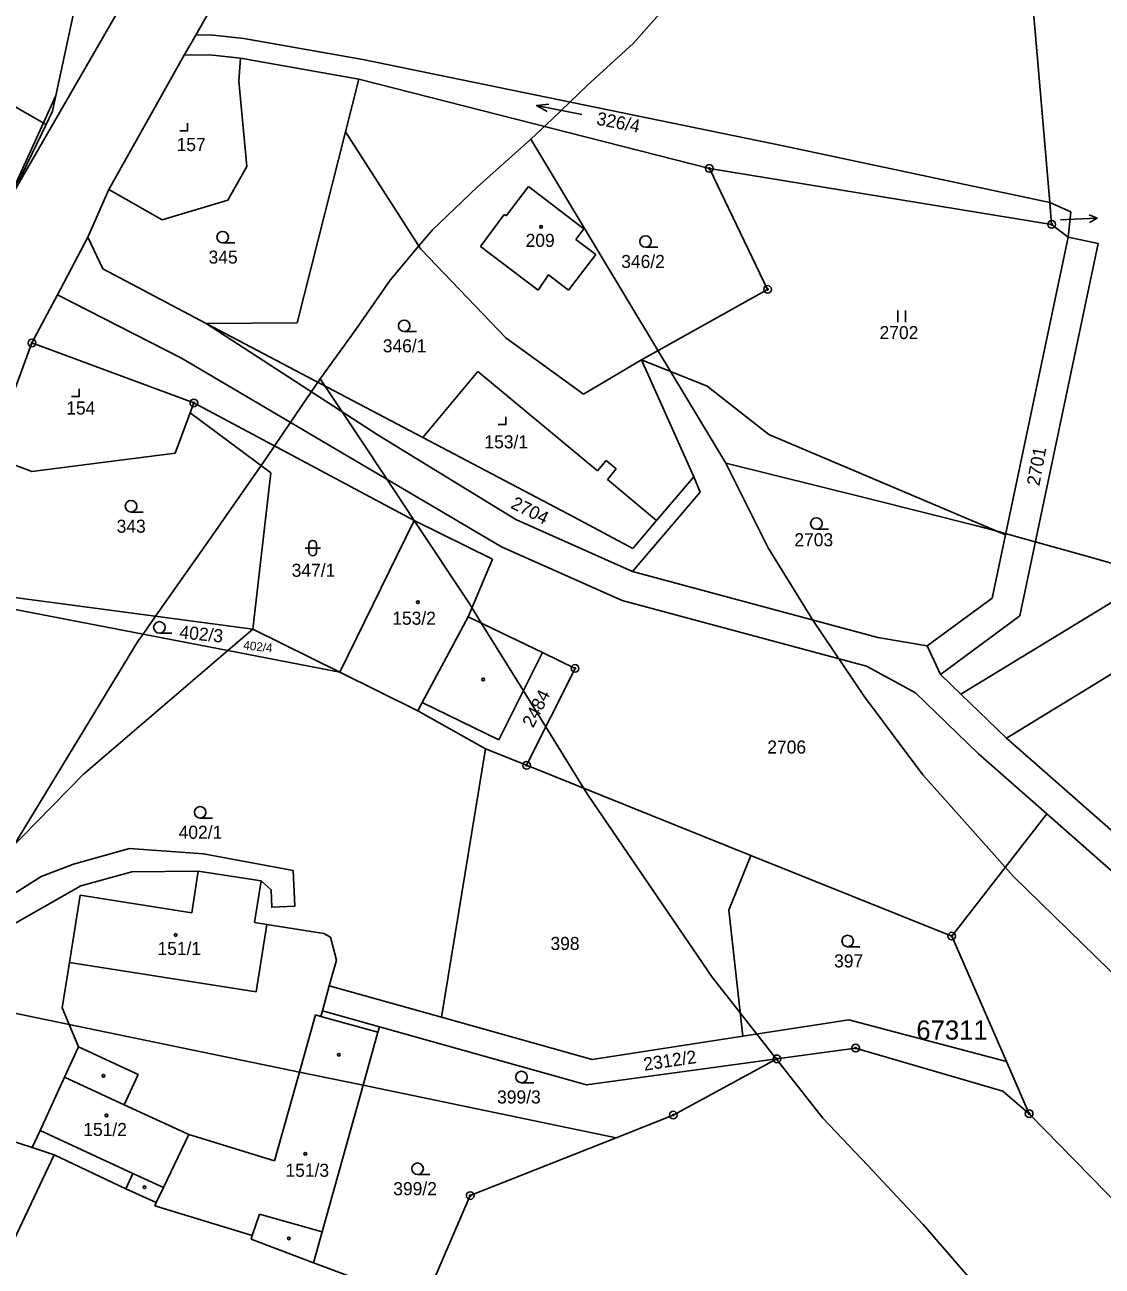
# Model space of a CAD drawing. Extents: x -546762 to -540209, y -1046851 to -1035694.
# Drawn here: x -542448.6 to -542308.1, y -1039131 to -1038969.2 of the extents above; entities that cross this region are included whole.
import ezdxf

# ---------------------------------------------------------------- set-up
doc = ezdxf.new("R2010")
doc.units = 0
for name, color, linetype in [('Vrstva 1', 7, 'Continuous'), ('Vrstva 16', 7, 'Continuous'), ('Vrstva 18', 7, 'Continuous'), ('Vrstva 19', 7, 'Continuous'), ('Vrstva 24', 7, 'Continuous'), ('Vrstva 25', 7, 'Continuous'), ('Vrstva 3', 7, 'Continuous'), ('Vrstva 30', 7, 'Continuous'), ('Vrstva 37', 7, 'Continuous'), ('Vrstva 4', 7, 'Continuous'), ('Vrstva 52', 7, 'Continuous'), ('Vrstva 53', 7, 'Continuous')]:
    doc.layers.add(name, color=color, linetype=linetype)

msp = doc.modelspace()

# ---------------------------------------------------------------- linework, layer by layer
at = {"layer": 'Vrstva 1'}
for p, q in [((-542405.08, -1038976.23), (-542359.35, -1038987.89)), ((-542349.73, -1038984.94), (-542314.95, -1038992.34)), ((-542437.67, -1038990.65), (-542440.39, -1038996.86)), ((-542424.99, -1039008.1), (-542413.11, -1039008.04)), ((-542375.74, -1039017.32), (-542368.19, -1039012.85)), ((-542396.72, -1039022.97), (-542389.53, -1039014.35)), ((-542372.63, -1039028.44), (-542366.22, -1039033.79)), ((-542386.81, -1039062.4), (-542381.12, -1039051.03)), ((-542410.99, -1039130.59), (-542396.61, -1039135.93))]:
    msp.add_line(p, q, dxfattribs=at)
for points in [[(-542450.21, -1038991.24), (-542389.73, -1038886.34)], [(-542426.34, -1038970.5), (-542407.76, -1038937.63)], [(-542440.93, -1038961.4), (-542445, -1038980.42)], [(-542317.12, -1038966.99), (-542314.95, -1038992.34)], [(-542426.34, -1038970.5), (-542427.82, -1038973.12)], [(-542426.34, -1038970.5), (-542424.46, -1038970.47)], [(-542424.46, -1038970.47), (-542420.06, -1038970.96)], [(-542420.06, -1038970.96), (-542404.56, -1038973.68)], [(-542437.67, -1038990.65), (-542427.82, -1038973.12)], [(-542427.82, -1038973.12), (-542424.55, -1038973.07)], [(-542424.55, -1038973.07), (-542420.48, -1038973.53)], [(-542420.48, -1038973.53), (-542420.7, -1038976.52)], [(-542420.48, -1038973.53), (-542405.08, -1038976.23)], [(-542404.56, -1038973.68), (-542349.73, -1038984.94)], [(-542420.7, -1038976.52), (-542419.68, -1038987.63)], [(-542405.08, -1038976.23), (-542406.82, -1038983.11)], [(-542454.29, -1038977.39), (-542445.83, -1038982.14)], [(-542445, -1038980.42), (-542445.83, -1038982.14)], [(-542450.21, -1038991.24), (-542445.83, -1038982.14)], [(-542413.11, -1039008.04), (-542406.82, -1038983.11)], [(-542406.82, -1038983.11), (-542396.96, -1038998.41)], [(-542419.68, -1038987.63), (-542422.16, -1038992.03)], [(-542314.71, -1038995.19), (-542359.35, -1038987.89)], [(-542359.35, -1038987.89), (-542351.76, -1039003.66)], [(-542430.7, -1038994.57), (-542437.67, -1038990.65)], [(-542385.85, -1038994.09), (-542382.94, -1038990.24)], [(-542382.94, -1038990.24), (-542375.7, -1038995.75)], [(-542422.16, -1038992.03), (-542430.7, -1038994.57)], [(-542314.95, -1038992.34), (-542312.2, -1038993.53)], [(-542314.95, -1038992.34), (-542314.71, -1038995.19)], [(-542389.19, -1038998.05), (-542386.09, -1038993.91)], [(-542386.09, -1038993.91), (-542385.85, -1038994.09)], [(-542312.2, -1038993.53), (-542312.56, -1038996.85)], [(-542375.7, -1038995.75), (-542376.75, -1038997.14)], [(-542314.71, -1038995.19), (-542312.56, -1038996.85)], [(-542444.38, -1039004.39), (-542440.39, -1038996.86)], [(-542440.39, -1038996.86), (-542438.47, -1039000.97)], [(-542376.75, -1038997.14), (-542374.17, -1038999.11)], [(-542312.56, -1038996.85), (-542320.72, -1039035.68)], [(-542312.56, -1038996.85), (-542308.65, -1038997.67)], [(-542396.96, -1038998.41), (-542385.88, -1039009.97)], [(-542381.68, -1039003.76), (-542389.19, -1038998.05)], [(-542374.17, -1038999.11), (-542377.71, -1039003.76)], [(-542308.65, -1038997.67), (-542318.86, -1039046.25)], [(-542438.47, -1039000.97), (-542424.99, -1039008.1)], [(-542380.34, -1039001.77), (-542381.68, -1039003.76)], [(-542377.71, -1039003.76), (-542380.34, -1039001.77)], [(-542351.76, -1039003.66), (-542368.19, -1039012.85)], [(-542447.69, -1039010.64), (-542444.38, -1039004.39)], [(-542444.38, -1039004.39), (-542428.18, -1039012.62)], [(-542402.56, -1039022.66), (-542424.99, -1039008.1)], [(-542424.99, -1039008.1), (-542396.72, -1039022.97)], [(-542385.88, -1039009.97), (-542375.74, -1039017.32)], [(-542447.69, -1039010.64), (-542453.15, -1039025.38)], [(-542447.69, -1039010.64), (-542426.58, -1039018.47)], [(-542428.18, -1039012.62), (-542386.44, -1039037.22)], [(-542359.65, -1039016.26), (-542368.19, -1039012.85)], [(-542368.19, -1039012.85), (-542361.38, -1039028.1)], [(-542389.53, -1039014.35), (-542373.95, -1039027.34)], [(-542351.59, -1039022.57), (-542359.65, -1039016.26)], [(-542426.58, -1039018.47), (-542427.07, -1039019.77)], [(-542426.58, -1039018.47), (-542397.83, -1039033.82)], [(-542427.07, -1039019.77), (-542429.01, -1039025.03)], [(-542416.54, -1039027.57), (-542427.07, -1039019.77)], [(-542384.57, -1039033.67), (-542402.56, -1039022.66)], [(-542376.96, -1039033.37), (-542396.72, -1039022.97)], [(-542320.72, -1039035.68), (-542351.59, -1039022.57)], [(-542447.73, -1039027.39), (-542429.01, -1039025.03)], [(-542453.15, -1039025.38), (-542447.73, -1039027.39)], [(-542373.95, -1039027.34), (-542372.81, -1039025.98)], [(-542372.81, -1039025.98), (-542371.49, -1039027.08)], [(-542416.54, -1039027.57), (-542418.9, -1039047.95)], [(-542372.63, -1039028.44), (-542371.49, -1039027.08)], [(-542366.22, -1039033.79), (-542361.38, -1039028.1)], [(-542361.38, -1039028.1), (-542360.53, -1039030.09)], [(-542326.56, -1039056.44), (-542283.01, -1039029.91)], [(-542360.53, -1039030.09), (-542369.38, -1039040.47)], [(-542407.53, -1039053.57), (-542397.83, -1039033.82)], [(-542397.83, -1039033.82), (-542387.63, -1039038.85)], [(-542369.38, -1039040.47), (-542384.57, -1039033.67)], [(-542376.96, -1039033.37), (-542369.32, -1039037.45)], [(-542369.32, -1039037.45), (-542366.22, -1039033.79)], [(-542320.72, -1039035.68), (-542322.46, -1039043.93)], [(-542386.44, -1039037.22), (-542370.72, -1039044.25)], [(-542387.63, -1039038.85), (-542390.82, -1039046.36)], [(-542320.61, -1039062.2), (-542281.44, -1039038.22)], [(-542337.36, -1039049.04), (-542369.38, -1039040.47)], [(-542459.49, -1039042.57), (-542418.9, -1039047.95)], [(-542459.82, -1039043.47), (-542422.16, -1039050.74)], [(-542370.72, -1039044.25), (-542338.86, -1039052.78)], [(-542322.46, -1039043.93), (-542330.92, -1039050.16)], [(-542390.82, -1039046.36), (-542381.12, -1039051.03)], [(-542318.86, -1039046.25), (-542329.22, -1039053.87)], [(-542422.16, -1039050.74), (-542418.9, -1039047.95)], [(-542418.9, -1039047.95), (-542407.53, -1039053.57)], [(-542330.92, -1039050.16), (-542337.36, -1039049.04)], [(-542441.01, -1039066.93), (-542422.16, -1039050.74)], [(-542422.16, -1039050.74), (-542407.53, -1039053.57)], [(-542381.12, -1039051.03), (-542376.86, -1039053.09)], [(-542330.92, -1039050.16), (-542329.22, -1039053.87)], [(-542397.35, -1039058.6), (-542407.53, -1039053.57)], [(-542376.86, -1039053.09), (-542383.18, -1039065.72)], [(-542338.86, -1039052.78), (-542332.48, -1039056.28)], [(-542329.22, -1039053.87), (-542326.56, -1039056.44)], [(-542396.82, -1039057.51), (-542397.35, -1039058.6)], [(-542386.81, -1039062.4), (-542396.82, -1039057.51)], [(-542332.48, -1039056.28), (-542324.31, -1039064.18)], [(-542326.56, -1039056.44), (-542320.61, -1039062.2)], [(-542397.35, -1039058.6), (-542388.54, -1039063.57)], [(-542320.61, -1039062.2), (-542275.85, -1039101.49)], [(-542394.29, -1039098.58), (-542388.54, -1039063.57)], [(-542388.54, -1039063.57), (-542383.18, -1039065.72)], [(-542324.31, -1039064.18), (-542315.34, -1039072.07)], [(-542453.05, -1039079.18), (-542441.01, -1039066.93)], [(-542383.18, -1039065.72), (-542353.93, -1039077.47)], [(-542315.34, -1039072.07), (-542327.73, -1039087.99)], [(-542315.34, -1039072.07), (-542286.16, -1039097.74)], [(-542353.93, -1039077.47), (-542356.8, -1039084.59)], [(-542353.93, -1039077.47), (-542327.73, -1039087.99)], [(-542426.01, -1039079.51), (-542426.86, -1039084.94)], [(-542426.01, -1039079.51), (-542417.8, -1039080.79)], [(-542417.8, -1039080.79), (-542418.65, -1039086.23)], [(-542441.41, -1039082.66), (-542442.8, -1039091.43)], [(-542426.86, -1039084.94), (-542441.41, -1039082.66)], [(-542356.8, -1039084.59), (-542354.99, -1039101.05)], [(-542418.65, -1039086.23), (-542417.08, -1039086.48)], [(-542417.08, -1039086.48), (-542409.63, -1039087.65)], [(-542408.75, -1039088.12), (-542409.63, -1039087.65)], [(-542407.96, -1039091.11), (-542408.75, -1039088.12)], [(-542327.73, -1039087.99), (-542320.6, -1039104.35)], [(-542442.8, -1039091.43), (-542443.74, -1039097.36)], [(-542407.96, -1039091.11), (-542408.91, -1039094.48)], [(-542477.81, -1039092.25), (-542442.85, -1039099.5)], [(-542408.91, -1039094.48), (-542409.82, -1039097.75)], [(-542394.29, -1039098.58), (-542408.91, -1039094.48)], [(-542443.74, -1039097.36), (-542442.85, -1039099.5)], [(-542409.82, -1039097.75), (-542402.38, -1039099.83)], [(-542442.85, -1039099.5), (-542441.62, -1039102.45)], [(-542442.85, -1039099.5), (-542412.82, -1039105.72)], [(-542374.65, -1039104.08), (-542394.29, -1039098.58)], [(-542354.99, -1039101.05), (-542341.15, -1039098.92)], [(-542341.15, -1039098.92), (-542320.6, -1039104.35)], [(-542402.58, -1039100.54), (-542404.51, -1039107.44)], [(-542402.38, -1039099.83), (-542402.58, -1039100.54)], [(-542402.38, -1039099.83), (-542375.38, -1039107.4)], [(-542374.65, -1039104.08), (-542354.99, -1039101.05)], [(-542441.62, -1039102.45), (-542443.44, -1039106.4)], [(-542441.62, -1039102.45), (-542433.83, -1039106.04)], [(-542340.27, -1039102.6), (-542350.54, -1039104)], [(-542321.08, -1039108.2), (-542340.27, -1039102.6)], [(-542375.38, -1039107.4), (-542350.54, -1039104)], [(-542350.54, -1039104), (-542364.06, -1039111.33)], [(-542320.6, -1039104.35), (-542317.64, -1039111.15)], [(-542433.83, -1039106.04), (-542435.65, -1039109.99)], [(-542412.82, -1039105.72), (-542404.51, -1039107.44)], [(-542443.44, -1039106.4), (-542446.64, -1039113.34)], [(-542404.51, -1039107.44), (-542409.86, -1039126.54)], [(-542404.51, -1039107.44), (-542371.5, -1039114.28)], [(-542317.64, -1039111.15), (-542321.08, -1039108.2)], [(-542435.65, -1039109.99), (-542427.25, -1039113.86)], [(-542364.06, -1039111.33), (-542371.5, -1039114.28)], [(-542301.62, -1039127.53), (-542317.64, -1039111.15)], [(-542446.64, -1039113.34), (-542447.67, -1039115.57)], [(-542427.25, -1039113.86), (-542430.54, -1039120.76)], [(-542447.67, -1039115.57), (-542450.87, -1039114.52)], [(-542447.67, -1039115.57), (-542444.8, -1039116.51)], [(-542371.5, -1039114.28), (-542390.54, -1039121.83)], [(-542444.8, -1039116.51), (-542453.5, -1039134.8)], [(-542435.44, -1039120.93), (-542444.8, -1039116.51)], [(-542431.49, -1039122.75), (-542435.44, -1039120.93)], [(-542431.49, -1039122.75), (-542430.54, -1039120.76)], [(-542390.54, -1039121.83), (-542396.61, -1039135.93)], [(-542431.68, -1039123.16), (-542431.49, -1039122.75)], [(-542418.96, -1039127.05), (-542431.68, -1039123.16)], [(-542419.09, -1039127.53), (-542418.96, -1039127.05)], [(-542409.86, -1039126.54), (-542410.99, -1039130.59)], [(-542410.99, -1039130.59), (-542419.09, -1039127.53)]]:
    msp.add_lwpolyline(points, dxfattribs=at)
at = {"layer": 'Vrstva 16'}
msp.add_line((-542311.78, -1038994.52), (-542308.78, -1038994.38), dxfattribs=at)
for points in [[(-542309.8, -1038993.93), (-542308.78, -1038994.38), (-542309.76, -1038994.93)], [(-542313.54, -1038994.6), (-542311.78, -1038994.52)]]:
    msp.add_lwpolyline(points, dxfattribs=at)
at = {"layer": 'Vrstva 24'}
for centre, radius in [((-542359.35, -1038987.89), 0.5), ((-542359.35, -1038987.89), 0.1), ((-542314.71, -1038995.19), 0.5), ((-542314.71, -1038995.19), 0.1), ((-542351.76, -1039003.66), 0.5), ((-542351.76, -1039003.66), 0.1), ((-542447.69, -1039010.64), 0.5), ((-542447.69, -1039010.64), 0.1), ((-542426.58, -1039018.47), 0.5), ((-542426.58, -1039018.47), 0.1), ((-542376.86, -1039053.09), 0.5), ((-542376.86, -1039053.09), 0.1), ((-542383.18, -1039065.72), 0.5), ((-542383.18, -1039065.72), 0.1), ((-542327.73, -1039087.99), 0.5), ((-542327.73, -1039087.99), 0.1), ((-542340.27, -1039102.6), 0.5), ((-542340.27, -1039102.6), 0.1), ((-542350.54, -1039104), 0.5), ((-542350.54, -1039104), 0.1), ((-542364.06, -1039111.33), 0.5), ((-542317.64, -1039111.15), 0.5), ((-542364.06, -1039111.33), 0.1), ((-542317.64, -1039111.15), 0.1), ((-542390.54, -1039121.83), 0.5), ((-542390.54, -1039121.83), 0.1)]:
    msp.add_circle(centre, radius, dxfattribs=at)
at = {"layer": 'Vrstva 25'}
for p, q in [((-542422.82, -1038997.6), (-542421.22, -1038997.6)), ((-542367.67, -1038998.17), (-542366.07, -1038998.17)), ((-542334.78, -1039007.93), (-542334.78, -1039006.43)), ((-542333.78, -1039007.93), (-542333.78, -1039006.43)), ((-542399.14, -1039009.17), (-542397.54, -1039009.17)), ((-542434.77, -1039032.69), (-542433.17, -1039032.69)), ((-542345.39, -1039034.95), (-542343.79, -1039034.95)), ((-542412.07, -1039037.39), (-542410.07, -1039037.39)), ((-542411.57, -1039037.89), (-542411.57, -1039036.89)), ((-542410.57, -1039036.89), (-542410.57, -1039037.89)), ((-542431.07, -1039048.49), (-542429.47, -1039048.49)), ((-542425.75, -1039072.6), (-542424.15, -1039072.6)), ((-542341.31, -1039089.38), (-542339.71, -1039089.38)), ((-542383.85, -1039107.12), (-542382.25, -1039107.12)), ((-542397.4, -1039119.08), (-542395.8, -1039119.08))]:
    msp.add_line(p, q, dxfattribs=at)
for points in [[(-542381.87, -1038979.7), (-542380.3, -1038979.49)], [(-542375.97, -1038980.84), (-542381.87, -1038979.7), (-542380.49, -1038980.48)], [(-542428.39, -1038983), (-542427.39, -1038983), (-542427.39, -1038982)], [(-542442.53, -1039017.61), (-542441.53, -1039017.61), (-542441.53, -1039016.61)], [(-542386.87, -1039021.26), (-542385.87, -1039021.26), (-542385.87, -1039020.26)]]:
    msp.add_lwpolyline(points, dxfattribs=at)
for centre, radius in [((-542381.3, -1038995.51), 0.175), ((-542422.82, -1038996.85), 0.75), ((-542367.67, -1038997.42), 0.75), ((-542399.14, -1039008.42), 0.75), ((-542434.77, -1039031.94), 0.75), ((-542345.39, -1039034.2), 0.75), ((-542397.36, -1039044.45), 0.175), ((-542431.07, -1039047.74), 0.75), ((-542388.84, -1039054.54), 0.175), ((-542425.75, -1039071.85), 0.75), ((-542428.95, -1039087.85), 0.175), ((-542341.31, -1039088.63), 0.75), ((-542407.68, -1039103.46), 0.175), ((-542438.37, -1039106.2), 0.175), ((-542383.85, -1039106.37), 0.75), ((-542437.96, -1039111.38), 0.175), ((-542412.04, -1039116.39), 0.175), ((-542397.4, -1039118.33), 0.75), ((-542433.01, -1039120.74), 0.175), ((-542414.19, -1039127.41), 0.175)]:
    msp.add_circle(centre, radius, dxfattribs=at)
for centre, start, end in [((-542411.07, -1039036.89), 0, 180), ((-542411.07, -1039037.89), 180, 0)]:
    msp.add_arc(centre, 0.5, start, end, dxfattribs=at)
at = {"layer": 'Vrstva 3'}
for points in [[(-542385.85, -1038994.09), (-542382.94, -1038990.24)], [(-542382.94, -1038990.24), (-542375.7, -1038995.75)], [(-542389.19, -1038998.05), (-542386.09, -1038993.91)], [(-542386.09, -1038993.91), (-542385.85, -1038994.09)], [(-542375.7, -1038995.75), (-542376.75, -1038997.14)], [(-542376.75, -1038997.14), (-542374.17, -1038999.11)], [(-542381.68, -1039003.76), (-542389.19, -1038998.05)], [(-542374.17, -1038999.11), (-542377.71, -1039003.76)], [(-542380.34, -1039001.77), (-542381.68, -1039003.76)], [(-542377.71, -1039003.76), (-542380.34, -1039001.77)], [(-542407.53, -1039053.57), (-542397.83, -1039033.82)], [(-542397.83, -1039033.82), (-542387.63, -1039038.85)], [(-542387.63, -1039038.85), (-542390.82, -1039046.36)], [(-542396.82, -1039057.51), (-542390.82, -1039046.36)], [(-542397.35, -1039058.6), (-542407.53, -1039053.57)], [(-542396.82, -1039057.51), (-542397.35, -1039058.6)], [(-542426.01, -1039079.51), (-542426.86, -1039084.94)], [(-542426.01, -1039079.51), (-542417.8, -1039080.79)], [(-542417.8, -1039080.79), (-542418.65, -1039086.23)], [(-542441.41, -1039082.66), (-542442.8, -1039091.43)], [(-542426.86, -1039084.94), (-542441.41, -1039082.66)], [(-542418.65, -1039086.23), (-542417.08, -1039086.48)], [(-542417.08, -1039086.48), (-542418.46, -1039095.25)], [(-542418.46, -1039095.25), (-542442.8, -1039091.43)], [(-542412.82, -1039105.72), (-542416.06, -1039117.28)], [(-542412.82, -1039105.72), (-542404.51, -1039107.44)], [(-542443.44, -1039106.4), (-542446.64, -1039113.34)], [(-542443.44, -1039106.4), (-542435.65, -1039109.99)], [(-542404.51, -1039107.44), (-542409.86, -1039126.54)], [(-542435.65, -1039109.99), (-542427.25, -1039113.86)], [(-542434.52, -1039118.93), (-542446.64, -1039113.34)], [(-542427.25, -1039113.86), (-542430.54, -1039120.76)], [(-542427.25, -1039113.86), (-542430.54, -1039120.76)], [(-542416.06, -1039117.28), (-542427.25, -1039113.86)], [(-542434.52, -1039118.93), (-542430.54, -1039120.76)], [(-542431.49, -1039122.75), (-542430.54, -1039120.76)], [(-542431.68, -1039123.16), (-542431.49, -1039122.75)], [(-542418.96, -1039127.05), (-542431.68, -1039123.16)], [(-542418.96, -1039127.05), (-542418.01, -1039124.26)], [(-542418.01, -1039124.26), (-542409.86, -1039126.54)]]:
    msp.add_lwpolyline(points, dxfattribs=at)
at = {"layer": 'Vrstva 30'}
for points in [[(-542454.56, -1039000.26), (-542446.19, -1038981.94), (-542444.56, -1038978.37), (-542445, -1038980.42), (-542445.83, -1038982.14), (-542450.21, -1038991.24), (-542454.56, -1039000.26)], [(-542457.73, -1039087.33), (-542446.51, -1039080.24), (-542442.26, -1039078.6), (-542434.98, -1039076.59), (-542425.3, -1039077.25), (-542413.63, -1039079.45), (-542413.41, -1039084.09), (-542416.41, -1039084.23), (-542416.51, -1039081.95), (-542417.8, -1039080.79), (-542426.01, -1039079.51), (-542434.68, -1039079.61), (-542441.32, -1039081.46), (-542455.91, -1039089.73), (-542462.28, -1039095.47), (-542465.92, -1039094.72), (-542457.73, -1039087.33)]]:
    msp.add_lwpolyline(points, dxfattribs=at)
at = {"layer": 'Vrstva 37'}
for centre in [(-542381.3, -1038995.51), (-542397.36, -1039044.45), (-542428.95, -1039087.85), (-542437.96, -1039111.38), (-542412.04, -1039116.39)]:
    msp.add_circle(centre, 0.175, dxfattribs=at)
at = {"layer": 'Vrstva 4'}
msp.add_line((-542396.82, -1039057.51), (-542390.82, -1039046.36), dxfattribs=at)
for points in [[(-542417.08, -1039086.48), (-542418.46, -1039095.25)], [(-542418.46, -1039095.25), (-542442.8, -1039091.43)], [(-542409.82, -1039097.75), (-542410.02, -1039098.46)], [(-542410.73, -1039098.26), (-542412.82, -1039105.72)], [(-542410.02, -1039098.46), (-542410.73, -1039098.26)], [(-542410.02, -1039098.46), (-542402.58, -1039100.54)], [(-542412.82, -1039105.72), (-542416.06, -1039117.28)], [(-542443.44, -1039106.4), (-542435.65, -1039109.99)], [(-542434.52, -1039118.93), (-542446.64, -1039113.34)], [(-542416.06, -1039117.28), (-542427.25, -1039113.86)], [(-542435.44, -1039120.93), (-542434.52, -1039118.93)], [(-542434.52, -1039118.93), (-542430.54, -1039120.76)], [(-542418.96, -1039127.05), (-542418.01, -1039124.26)], [(-542418.01, -1039124.26), (-542409.86, -1039126.54)]]:
    msp.add_lwpolyline(points, dxfattribs=at)
at = {"layer": 'Vrstva 52'}
for points in [[(-542330.33, -1038913.06), (-542332.56, -1038917.03), (-542341.34, -1038932.65), (-542343.36, -1038936.25), (-542349.37, -1038946.45), (-542355.12, -1038955.08), (-542359.2, -1038960.01), (-542361.4, -1038962.67), (-542369.24, -1038971.56), (-542375.25, -1038977.05), (-542377.53, -1038979.23), (-542379.82, -1038981.42), (-542382.61, -1038984.08)], [(-542382.61, -1038984.08), (-542389.63, -1038990.35), (-542395.45, -1038995.88), (-542397.23, -1038997.99), (-542400.98, -1039002.46), (-542405.46, -1039008.88), (-542410.09, -1039015.31)], [(-542357.19, -1039026.31), (-542365.96, -1039011.74), (-542382.61, -1038984.08)], [(-542410.09, -1039015.31), (-542413.09, -1039019.71), (-542415.01, -1039022.53), (-542417.11, -1039025.62), (-542417.81, -1039026.63), (-542425.03, -1039036.98), (-542431.57, -1039046.27), (-542433.21, -1039048.61), (-542433.84, -1039049.5), (-542450.05, -1039076.17)], [(-542410.09, -1039015.31), (-542404.21, -1039024.18), (-542400.47, -1039029.84), (-542397.83, -1039033.82), (-542390.6, -1039044.72), (-542390.56, -1039044.79), (-542388.96, -1039047.36), (-542383.6, -1039055.99), (-542380.67, -1039060.71), (-542375.7, -1039068.73), (-542375.18, -1039069.56), (-542358.98, -1039093.36), (-542355.32, -1039098.01), (-542353.15, -1039100.77), (-542350.59, -1039104.02), (-542344.53, -1039111.73), (-542338.7, -1039117.91), (-542334.2, -1039122.69), (-542331.46, -1039125.6), (-542323.89, -1039134.33), (-542321.27, -1039137.36), (-542313.69, -1039146.52), (-542307.68, -1039154.89)], [(-542305.39, -1039094.17), (-542319.73, -1039080.18), (-542327.48, -1039071.47), (-542331.5, -1039066.96), (-542335.49, -1039061.63), (-542338.17, -1039058.06), (-542339.12, -1039056.8), (-542345.84, -1039046.78), (-542351.67, -1039037.37), (-542357.19, -1039026.31)], [(-542357.19, -1039026.31), (-542338.63, -1039030.94), (-542324.65, -1039034.43), (-542322.62, -1039034.99), (-542309.49, -1039038.61), (-542296.01, -1039042.49), (-542292.15, -1039043.6), (-542288.58, -1039044.63), (-542274.2, -1039049.86), (-542265.32, -1039053.52), (-542256.95, -1039057.71), (-542247.28, -1039064.24), (-542239.7, -1039071.04), (-542232.12, -1039080.72), (-542225.13, -1039092.23), (-542224.42, -1039093.34), (-542220.07, -1039100.12), (-542218.59, -1039102.43), (-542215.63, -1039108.01), (-542212.06, -1039114.72)]]:
    msp.add_lwpolyline(points, dxfattribs=at)

# ---------------------------------------------------------------- texts
at = {"layer": 'Vrstva 18'}
for s, height, rotation, p in [('326/4', 1.7, 349.0147, (-542374.16, -1038982.16)), ('2701', 1.7, 79.5732, (-542316.31, -1039029.36)), ('2704', 1.7, 333.4041, (-542385.37, -1039032.11)), ('402/3', 1.7, 354.1689, (-542428.52, -1039049.15)), ('402/4', 1.14, 353.9622, (-542420.17, -1039050.6)), ('2484', 1.7, 63, (-542382.33, -1039060.93)), ('2312/2', 1.7, 8.4822, (-542367.81, -1039105.56))]:
    msp.add_text(s, height=height, rotation=rotation, dxfattribs=at).set_placement(p)
for s, height, p in [('2728', 0.1, (-542313.68, -1038994.65)), ('345', 1.7, (-542424.66, -1039000.3)), ('346/2', 1.7, (-542370.84, -1039000.87)), ('2702', 1.7, (-542337.15, -1039010.14)), ('346/1', 1.7, (-542401.94, -1039011.87)), ('343', 1.7, (-542436.65, -1039035.39)), ('2703', 1.7, (-542348.26, -1039037.16)), ('347/1', 1.7, (-542413.82, -1039041.14)), ('2706', 1.7, (-542351.79, -1039064.19)), ('402/1', 1.7, (-542428.56, -1039075.3)), ('398', 1.7, (-542380.07, -1039089.8)), ('397', 1.7, (-542343.08, -1039092.08)), ('399/3', 1.7, (-542387.03, -1039109.82)), ('399/2', 1.7, (-542400.57, -1039121.78))]:
    msp.add_text(s, height=height, dxfattribs=at).set_placement(p)
at = {"layer": 'Vrstva 19'}
for s, p in [('157', (-542428.83, -1038985.63)), ('209', (-542383.31, -1038998.12)), ('154', (-542443.22, -1039019.98)), ('153/1', (-542388.68, -1039024.39)), ('153/2', (-542400.7, -1039047.39)), ('151/1', (-542431.32, -1039090.45)), ('151/2', (-542441, -1039114.06)), ('151/3', (-542414.63, -1039119.38))]:
    msp.add_text(s, height=1.7, dxfattribs=at).set_placement(p)
at = {"layer": 'Vrstva 53'}
msp.add_text('67311', height=2.5, dxfattribs=at).set_placement((-542332.35, -1039101.49))

doc.saveas('drawing.dxf')
